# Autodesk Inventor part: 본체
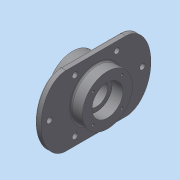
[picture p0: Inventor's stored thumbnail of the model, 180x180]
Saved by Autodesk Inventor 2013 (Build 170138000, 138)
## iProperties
Created: 2015-02
Part Number: 본체
Material: 일반
Document SubType Name: Modeling
Designer: Administrator
Density: 1 g/cm^3
Author: Administrator
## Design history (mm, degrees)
sketch "스케치1" dims "d51" = 50
  geometry: L1 (-154, 0)-(154, 0) reference; L2 (0, -98)-(0, 98) reference; L3 (60, 70)-(-60, 70); L4 (-60, 70)-(-60, -70); L5 (-60, -70)-(60, -70); L6 (60, -70)-(60, 70); 3 further points; 2 other entities
  constraints: 8 end point, 2 parallel, 2 vertical, 1 horizontal, 1 midpoint, 1 perpendicular, 1 symmetric about line, 10 other
  dimensions: "d1" = 140 distance of L4.end L3.end; "d3" = 120 distance between parallel lines of L4 L6
extrude "돌출1" new body sketch "스케치1" distance "d5" = 12; taper "d6" = 0 deg
sketch "스케치2"
  geometry: C1 r 50 at (0, 0); 1 further point
  constraints: 1 centre point, 1 coincident
  dimensions: "d7" = 100 diameter of C1
extrude "돌출2" join sketch "스케치2" distance "d9" = 23; taper "d11" = 0 deg; dims "d10" = 47, "d12" = 0
sketch "스케치3"
  geometry: L1 (0, 60)-(0, -60) reference; L2 (-35, 0)-(35, 0); L3 (-35, 0)-(-35, 31); L4 (-35, 31)-(-13, 31); L5 (-13, 31)-(-13, 22.5); L6 (-13, 22.5)-(13, 22.5); L7 (13, 22.5)-(13, 31); L8 (13, 31)-(35, 31); L9 (35, 31)-(35, 0); L10 (-35, 50)-(-35, -50) reference; L11 (35, -50)-(35, 50) reference; 5 further points
  constraints: 16 end point, 5 midpoint, 4 perpendicular, 4 point on line, 3 parallel, 2 vertical alignment, 1 collinear
  dimensions: "d13" = 22 distance between parallel lines of L9 L7; "d15" = 22 distance between parallel lines of L5 L3; "d16" = 62 diameter of L4 L2; "d17" = 62 diameter of L8 L2; "d18" = 45 diameter of L6 L2
revolve "회전1" sketch "스케치3" stored, may be unused: angle "d19" = 90 deg
sketch "스케치6" dims "d34" = 82
  geometry: L1 (0, 0)-(-28.991, 28.991); L2 (-98, 0)-(98, 0) reference; C1 r 50 at (0, 0) reference; 1 further point
  constraints: 2 coincident, 2 end point, 3 other
  dimensions: "d36" = 45 deg angle of L2 L1
hole "구멍1" sketch "스케치6" at (-28.991, 28.991) diameter "d38" = 4.917; stored, may be unused: countersink angle "d42" = 90 deg, drill point angle "d44" = 118 deg; dims "d39" = 10, "d40" = 4, "d41" = 2, "d43" = 13
node "작업 평면1"
sketch "스케치8" dims "d53" = 17
  geometry: L1 (70, 60)-(70, -60) reference; L2 (-70, -60)-(-70, 60) reference; L3 (53, 60)-(53, -60); L4 (-53, -60)-(-53, 60); L5 (0, -154)-(0, 154) reference; L6 (-98, 0)-(98, 0) reference; L7 (-82.976, 42)-(82.976, 42); C1 r 10 at (0, 93); C2 r 50 at (0, 0) reference; C3 r 10 at (-53, 42); C4 r 10 at (53, 42); A1 r 93 centre (0, 0) between (0, 93) and (82.976, 42); 2 further points; 2 other entities
  constraints: 6 end point, 5 point on line, 4 centre point, 4 parallel, 3 point on circle, 1 coincident, 1 horizontal alignment, 8 other
  dimensions: "d55" = 20 diameter of C1; "d62" = 42 distance between parallel lines of L6 L7; "d63" = 20 diameter of C4; "d64" = 20 diameter of C3
extrude "돌출6" join sketch "스케치8" distance "d65" = 5; taper "d66" = 0 deg
sketch "스케치9"
  geometry: C1 r 10 at (0, 0) reference; C2 r 5.5 at (0, 0); C3 r 10 at (-53, -135) reference; C4 r 10 at (0, -186) reference; C5 r 10 at (53, -135) reference; C6 r 10 at (-53, -51) reference; C7 r 10 at (0, 0) reference; C8 r 10 at (53, -51) reference; C9 r 22.5 at (0, -93) reference; C10 r 50 at (0, -93) reference; C11 r 5.5 at (-53, -51); C12 r 5.5 at (53, -51); C13 r 5.5 at (53, -135); C14 r 5.5 at (0, -186); C15 r 5.5 at (-53, -135); 1 further point
  constraints: 6 centre point, 6 coincident, 5 equal radius
  dimensions: "d67" = 11 diameter of C2
extrude "돌출7" cut sketch "스케치9" stored distance "d69" = 5; taper "d70" = 0 deg
fillet "모깎기1" dims "d71" = 0.3
fillet "모깎기2" dims "d72" = 3
sketch "스케치10"
  geometry: C1 r 53 at (0, 0) reference; 1 further point
  constraints: 1 vertical alignment, 1 other
  dimensions: "d73" = 65 distance of C1.centre point (0, 65)
feature "엠보싱1" sketch "스케치10" dims "d1" = 140, "d3" = 120, "d13" = 22, "d15" = 22, "d16" = 62, "d17" = 62, "d18" = 45, "d51" = 50, "d74" = 1, "d75" = 0
node "솔리드1"
pattern_circular "원형 패턴1" dims angle "d46" = 360 deg
mirror "대칭1"
mirror "대칭2"
node "절단 모서리 투영4"
